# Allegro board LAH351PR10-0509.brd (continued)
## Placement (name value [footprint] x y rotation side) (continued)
CV1068  10U_0603_6.3V6M~D  [C_0603]  130.24 151.22 180 bottom
CV1069  0.1U_0201_6.3V6K  [C_0201]  131.06 151.06 90 bottom
CV1071  10P_0402_50V8J  [C_0402]  40.64 143.3 270 top
CV1074  10P_0402_50V8J  [C_0402]  101.73 138.64 90 bottom
CV1075  10P_0402_50V8J  [C_0402]  30.9 140.97 180 bottom
CV1076  10U_0603_6.3V6M  [C_0603]  31.11 140.01 270 bottom
CV1077  10U_0603_6.3V6M  [C_0603]  32.26 139.35 0 bottom
CV1078  47U_0603_6.3V6M  [C_0603]  28.64 139.91 0 bottom
CV1079  10U_0603_6.3V6M  [C_0603]  28.64 138.7 0 bottom
CV1080  10P_0402_50V8J  [C_0402]  29.12 141 180 bottom
CV1081  2200P_0402_25V7K  [C_0402]  27.22 140.08 270 bottom
CV7160  0.1U_0402_16V4Z  [C_0402]  80.31 14.12 0 bottom
CV7161  4.7U_0402_6.3V6M  [C_0402]  80.31 13.11 0 bottom
CX1  0.1U_0402_16V7K  [C_0402]  121.87 142.78 180 top
CX2  0.1U_0402_16V7K  [C_0402]  129.84 143.22 0 top
CZ120  0.1U_0402_10V7K  [C_0402]  81.32 6.78 270 bottom
CZ121  470P_0402_50V7K  [C_0402]  82.27 9.76 90 bottom
DE1  SDMK0340L-7-F_SOD323-2~D  [SDMK0340L-7-F_SOD323-2]  115.44 20.21 270 bottom
DE2  -  [RB751V-40_SOD323-2]  74.23 7.4 90 top
DE3  -  [RB751V-40_SOD323-2]  72.58 7.4 90 top
DF1  -  [SDMK0340L-7-F_SOD323-2]  85.28 21.68 270 top
DF2  -  [SDMK0340L-7-F_SOD323-2]  87 21.68 270 top
DG2  RB751S40T1G_SOD523-2  [RB520SM-30T2R_EMD2-2]  61.82 76.8 90 top
DG3  RB751S40T1G_SOD523-2  [RB520SM-30T2R_EMD2-2]  77.6 57.27 270 bottom
DG4  RB751S40T1G_SOD523-2  [RB520SM-30T2R_EMD2-2]  77.6 59.25 90 bottom
DG7  RB751S40T1G_SOD523-2  [RB520SM-30T2R_EMD2-2]  76.33 57.27 270 bottom
DG8  RB751S40T1G_SOD523-2  [RB520SM-30T2R_EMD2-2]  98.33 55.11 180 top
DG9  RB751S40T1G_SOD523-2  [RB520SM-30T2R_EMD2-2]  95.53 53.64 90 top
DG10  RB751S40T1G_SOD523-2  [RB520SM-30T2R_EMD2-2]  73.24 56.86 90 bottom
DH1  -  [RB751V-40_SOD323-2]  111.76 17.75 90 top
DK1  -  [TVNST52302AB0_SOT523-3]  89.04 9.5 0 top
DK2  -  [TVNST52302AB0_SOT523-3]  70.1 82.07 0 bottom
DK3  -  [TVNST52302AB0_SOT523-3]  81.85 11.58 90 bottom
DT1  SDM10U45-7_SOD523-2~D  [RB520SM-30T2R_EMD2-2]  100.27 145.74 90 bottom
DT2  -  [PESD5V0H1BSF_SOD962-2-2]  91 148.67 90 bottom
DT3  -  [PESD5V0H1BSF_SOD962-2-2]  91 147.93 270 bottom
DT4  -  [PESD5V0H1BSF_SOD962-2-2]  94.24 147.22 180 top
DT5  -  [PESD5V0H1BSF_SOD962-2-2]  94.99 147.22 0 top
DT6  -  [PESD5V0H1BSF_SOD962-2-2]  99.37 147.22 0 top
DT7  -  [PESD5V0H1BSF_SOD962-2-2]  98.62 147.22 180 top
DT8  -  [PESD5V0H1BSF_SOD962-2-2]  99.18 148.87 0 bottom
DT9  -  [PESD5V0H1BSF_SOD962-2-2]  98.5 148.87 180 bottom
DT10  -  [TVWDF1004AD0_DFN9]  102.88 148.79 270 bottom
DT11  -  [PESD5V0H1BSF_SOD962-2-2]  95.96 151.92 180 bottom
DT12  -  [PESD5V0H1BSF_SOD962-2-2]  97.15 147.22 0 top
DT13  -  [PESD5V0H1BSF_SOD962-2-2]  97.65 151.92 0 bottom
DT14  -  [PESD5V0H1BSF_SOD962-2-2]  96.07 147.22 0 top
DT15  -  [PESD24VS2UT_SOT23-3]  105.22 145.39 0 bottom
DT16  -  [PESD5V0H1BSF_SOD962-2-2]  138.88 55.93 180 bottom
DU6  -  [SDMK0340L-7-F_SOD323-2]  82.87 6.44 0 bottom
DU8  -  [SDMK0340L-7-F_SOD323-2]  87.63 10.5 270 bottom
DV1  -  [RB751V-40_SOD323-2]  24.93 133.96 90 top
DV4  -  [AZC199-02SPR7G_SOT23-3]  66.97 138.85 270 bottom
DV12  SDM10U45-7_SOD523-2  [RB520SM-30T2R_EMD2-2]  136.68 151.28 180 bottom
DV13  SDM10U45-7_SOD523-2  [RB520SM-30T2R_EMD2-2]  136.68 150.01 180 bottom
FD1  FIDUCIAL  [FIDUCIAL_C40M80]  11.49 138.46 0 top
FD2  FIDUCIAL  [FIDUCIAL_C40M80]  146.56 35.02 0 top
FD3  FIDUCIAL  [FIDUCIAL_C40M80]  12.51 138.46 180 bottom
FD4  FIDUCIAL  [FIDUCIAL_C40M80]  125.22 11.08 180 bottom
FV2  1.1A_6V_SPR-P110  [F_SPR-P110]  103.93 143.54 0 top
FV3  1.1A_6V_SPR-P110  [F_SPR-P110]  128.25 149.63 0 bottom
FV4  1.5A_24V_SMD1812P150TF-24  [F_SMD1812P150TF-24]  34.49 142.78 180 top
H1  -  [H_4P0]  149.5 114.4 0 top
H2  -  [H_3P7-G]  144.9 80.1 0 top
H3  -  [H_2P6-G]  140 44.5 0 top
H4  -  [H_2P6-G]  42.4 2.5 0 top
H5  -  [H_2P6-G]  7 44.5 0 top
H6  -  [H_4P3X3P7-G]  7.6 66.7 0 top
H7  -  [H_4P0-G]  6.5 140 0 top
H10  -  [H_2P6-G]  87.67 152.7 0 top
H11  -  [H_2P6-G]  106 152.7 0 top
H12  -  [H_1P8]  122.3 149.75 90 top
H13  -  [H_2P6-G]  142.89 149.6 0 top
H14  -  [H_4P0-G]  70.5 128.95 0 top
H15  -  [H_4P0-G]  66.1 68.3 0 top
J4  -  [JUMP_43X79]  63.08 11.27 0 bottom
J5  -  [JUMP_43X79]  72.88 11.78 180 bottom
J6  -  [JUMP_43X79]  103.1 17.43 180 top
JCDRA  TE_2260531-1  [TE_2260531-1_46P]  54.6 149.25 180 top
JDP  ACON_MAR2A-2061801  [ACON_MAR2A-2061801_20P]  112.2 145.82 180 top
JEDP  ACES_50473-0400M-P01  [ACES_50473-0400M-P01_40P]  55.75 151.32 180 bottom
JELC2  CVILU_CH51102M100-0P  [CVILU_CH51102M100-0P_10P-T]  132.95 15.52 90 top
JFAN1  CVILU_CI4204M2HR0-NH  [CVILU_CI4204M2HR0-NH_4P]  14.86 50.89 90 bottom
JFAN2  CVILU_CI4204M2HR0-NH  [CVILU_CI4204M2HR0-NH_4P]  145.05 46.43 270 bottom
JGYRO  ACES_50208-00601-P01  [ACES_50208-00601-P01_6P]  25.12 132.61 270 bottom
JHDMI  ACON_HMRF5-AK1L0C  [ACON_HMRF5-AK1L0C_19P]  127.8 145.68 180 top
JIO1  UNIMI_FBGCAX011  [UNIMI_FBGCAX011_68P-T]  10.66 5.44 90 bottom
JIO2  UNIMI_FBGCAX011  [UNIMI_FBGCAX011_68P-T]  142.34 35.96 270 bottom
JP1  PAD-OPEN 43X39  [JUMP_43X39]  93.61 39.78 180 bottom
JPCMC  INTEL_CMC_PRIMARY  [INTEL_CMC_PRIMARY_36P-T]  147.44 144.74 0 top
JPK  CVILU_CF5020FD0RK-05-NH  [CVILU_CF5020FD0RK-05-NH_20P]  76.45 7.42 180 bottom
JPTRON  ACES_50208-01201-P01  [ACES_50208-01201-P01_12P-T]  51.71 1.5 0 bottom
JRTC1  TWVM_WTB1220-02RD-MAGHB  [TWVM_WTB1220-02RD-MAGHB_2P]  17.73 13.07 180 bottom
JSSD1  LOTES_YPCI0020-P001A  [LOTES_YPCI0020-P001A_75P-T]  111.85 8.87 0 top
JSSD3  LOTES_YPCI0020-P001A  [LOTES_YPCI0020-P001A_75P-T]  136.65 8.87 0 top
JTOBII  HRS_DF52-6S-0P8H(21)  [HRS_DF52-6S-0P8H-21_6P-T]  142.92 142.31 270 bottom
JTP15  STARC_106A08-001020-A2-R  [STARC_106A08-001020-A2-R_8P]  76.16 4.73 0 top
JTP17  ACES_51678-0080N-001  [ACES_51678-0080N-001_8P-T]  60.31 5.93 0 top
JUSBC  JAE_DX07SA24XJ2R1000~D  [JAE_DX07SA24XJ2R1000_24P]  99.58 148.79 180 top
JWDB  ACES_88266-04001  [ACES_50207-00471-P01_4P-T]  123.35 43.61 270 top
JWDB1  ACES_88266-04001  [ACES_50207-00471-P01_4P-T]  135.87 15.86 270 top
LE1  FBMA-L11-160808-800LMT_0603  [KC_FBMA-L11-160808-800LMT_2P]  76.89 20.54 180 top
LE3  DLM0NSN900HY2D_4P  [MURAT_DLM0NSN900HY2D_4P]  140.16 140.24 0 bottom
LE4  BLM15AG121SN1D_L0402_2P  [MURAT_BLM15AG121SN1D_L0402_2P]  128.52 26.04 270 bottom
LE5  FBMA-L11-160808-800LMT_0603  [KC_FBMA-L11-160808-800LMT_2P]  73.35 19.01 0 top
LE7  DLM0NSN900HY2D_4P  [MURAT_DLM0NSN900HY2D_4P]  89.94 11.19 270 top
LG1  PBY160808T-301Y-N  [CHILI_PBY160808T-300Y-N_2P]  51.65 104.58 0 bottom
LG6  PBY160808T-300Y-N_2P  [CHILI_PBY160808T-300Y-N_2P]  50.53 111.28 0 bottom
LG8  PBY160808T-300Y-N_2P  [CHILI_PBY160808T-300Y-N_2P]  50.25 87.9 0 bottom
LG9  PBY160808T-300Y-N_2P  [CHILI_PBY160808T-300Y-N_2P]  59.83 94.26 180 bottom
LG10  PBY160808T-300Y-N_2P  [CHILI_PBY160808T-300Y-N_2P]  59.77 97.06 180 bottom
LM1  DLM0NSN900HY2D_4P  [MURAT_DLM0NSN900HY2D_4P]  38.1 145.58 90 top
LT1  0.6UH_MND-04ABIR60M-XGL_20%  [MAG_MND-04ABIR60M-XGL_2P]  71.35 148.49 0 top
LT2  DLM0NSN900HY2D_4P  [MURAT_DLM0NSN900HY2D_4P]  95.81 143.17 90 top
LT3  DLM0NSN900HY2D_4P  [MURAT_DLM0NSN900HY2D_4P]  97.41 143.17 90 top
LT4  1UH_LQM18PN1R0MFHD_20%  [MURAT_LQM18PN1R0MFHD_2P]  84.71 145.75 90 top
LV2  DLM0NSN900HY2D_4P  [MURAT_DLM0NSN900HY2D_4P]  66 134.8 90 bottom
LV3  HCM1012GH900BP_4P  [INPAQ_HCM1012GH900BP_4P-NPM]  138.36 139.99 90 bottom
LV4  HCM1012GH900BP_4P  [INPAQ_HCM1012GH900BP_4P-NPM]  134.11 140.06 90 bottom
LV5  HCM1012GH900BP_4P  [INPAQ_HCM1012GH900BP_4P-NPM]  124.58 139.93 90 bottom
LV6  HCM1012GH900BP_4P  [INPAQ_HCM1012GH900BP_4P-NPM]  129.35 139.99 90 bottom
LX1  PBY100505T-601Y-N_2P  [CHILI_PBY100505T-300Y-N_2P]  135.64 138.21 90 bottom
LX2  PBY100505T-601Y-N_2P  [CHILI_PBY100505T-300Y-N_2P]  132.14 138.21 90 bottom
LX3  PBY100505T-601Y-N_2P  [CHILI_PBY100505T-300Y-N_2P]  140.4 138.21 90 bottom
LX4  PBY100505T-601Y-N_2P  [CHILI_PBY100505T-300Y-N_2P]  136.84 138.21 90 bottom
LX5  PBY100505T-601Y-N_2P  [CHILI_PBY100505T-300Y-N_2P]  126.17 138.21 90 bottom
LX6  PBY100505T-601Y-N_2P  [CHILI_PBY100505T-300Y-N_2P]  122.62 138.21 90 bottom
LX7  PBY100505T-601Y-N_2P  [CHILI_PBY100505T-300Y-N_2P]  130.94 138.21 90 bottom
LX8  PBY100505T-601Y-N_2P  [CHILI_PBY100505T-300Y-N_2P]  127.38 138.21 90 bottom
NOREF  -  []  7.6 66.7 0 top
NOREF#2  -  []  42.4 2.5 0 top
NOREF#3  -  []  140 44.5 0 top
NOREF#4  -  []  142.89 149.6 0 top
NOREF#5  -  []  6.5 140 0 top
NOREF#6  -  []  21.34 199.93 0 top
NOREF#7  -  []  87.67 152.7 0 top
NOREF#8  -  []  70.5 128.95 0 top
NOREF#9  -  []  7 44.5 0 top
NOREF#10  -  []  82.79 82.54 270 top
NOREF#11  -  []  55.19 -33.83 0 top
NOREF#12  -  []  162.94 52.22 0 top
NOREF#13  -  []  65.28 -31.95 0 top
NOREF#14  -  []  106 152.7 0 top
NOREF#15  -  []  66.1 68.3 0 top
NOREF#16  -  []  149.5 114.4 0 top
NOREF#17  -  []  0 157 0 top
NOREF#18  -  []  0 157 0 top
NOREF#19  -  []  104.33 81.05 0 top
NOREF#20  -  []  0 157 0 top
NOREF#21  -  []  144.9 80.1 0 top
NOREF#22  -  []  122.75 77.5 0 top
NOREF#23  -  []  132.03 47.75 180 bottom
NOREF#24  -  []  42.08 17.24 90 bottom
NOREF#25  -  []  132.94 79.68 270 bottom
PBATT1  OCTEK_WTB-10FPBLAB-U  [OCTEK_WTB-10FPBLAB-U_10P]  24.58 9.95 180 bottom
PC1  100P_0402_50V8J  [C_0402]  10.54 37.1 90 bottom
PC2  1000P_0402_50V7K  [C_0402]  9.59 37.1 90 bottom
PC3  100P_0402_50V8J  [C_0402]  11.37 26.84 270 bottom
PC4  1000P_0402_50V7K  [C_0402]  12.32 26.84 270 bottom
PC6  1000P_0402_50V7K  [C_0402]  32.7 4.83 270 top
PC7  100P_0402_50V8J  [C_0402]  36.07 4.77 270 top
PC8  1000P_0402_50V7K  [C_0402]  37.5 9.68 0 top
PC9  100P_0402_50V8J  [C_0402]  37.5 10.76 0 top
PC13  .1U_0402_16V7K  [C_0402]  50.1 12.27 90 top
PC14  1U_0603_25V6K  [C_0603]  25.87 4.9 180 top
PC15  0.1U_0402_25V6  [C_0402]  17.54 1.93 180 top
PC301  1U_0402_25V6K  [C_0402]  67.28 34.58 0 top
PC302  22U_0603_6.3V6M  [C_0603]  60.77 18.76 90 bottom
PC303  22U_0603_6.3V6M  [C_0603]  63.18 18.76 90 bottom
PC304  22U_0603_6.3V6M  [C_0603]  61.98 18.76 90 bottom
PC305  22U_0603_6.3V6M  [C_0603]  64.39 18.76 90 bottom
PC306  22U_0603_6.3V6M  [C_0603]  65.6 18.76 90 bottom
PC307  10U_0603_25V6M  [C_0603]  65.34 28.54 180 top
PC308  10U_0603_25V6M  [C_0603]  65.34 28.54 180 bottom
PC309  4.7U_0402_6.3V6M  [C_0402]  60.34 21.92 0 top
PC310  680P_0402_50V7K  [C_0402]  65.21 26.72 0 bottom
PC311  1000P_0402_25V8J  [C_0402]  64.14 34.14 270 bottom
PC312  0.1U_0402_25V6  [C_0402]  65.42 29.68 180 bottom
PC313  1000P_0402_25V8J  [C_0402]  59.94 24.42 270 bottom
PC314  2200P_0402_50V7K  [C_0402]  65.41 29.68 180 top
PC315  .1U_0402_16V7K  [C_0402]  68.16 23.05 270 top
PC501  1U_0402_25V6K  [C_0402]  59.66 35.89 180 top
PC502  22U_0603_6.3V6M  [C_0603]  56.07 14.82 90 bottom
PC503  22U_0603_6.3V6M  [C_0603]  56.07 13.17 270 bottom
PC504  22U_0603_6.3V6M  [C_0603]  53.53 14.82 90 bottom
PC505  22U_0603_6.3V6M  [C_0603]  54.8 14.82 90 bottom
PC506  22U_0603_6.3V6M  [C_0603]  54.8 13.17 270 bottom
PC507  22U_0603_6.3V6M  [C_0603]  53.53 13.17 270 bottom
PC508  10U_0603_25V6M  [C_0603]  57.02 27.59 180 top
PC509  10U_0603_25V6M  [C_0603]  59.44 26.82 0 top
PC510  4.7U_0402_6.3V6M  [C_0402]  54.37 21.87 180 bottom
PC511  4.7U_0402_6.3V6M  [C_0402]  41.85 9.69 270 bottom
PC512  4.7U_0402_6.3V6M  [C_0402]  54.39 22.81 180 bottom
PC513  680P_0402_50V7K  [C_0402]  52.83 19.71 0 bottom
PC514  1000P_0402_25V8J  [C_0402]  59.96 34.98 180 top
PC515  0.1U_0402_25V6  [C_0402]  56.72 26.49 180 top
PC516  1000P_0402_25V8J  [C_0402]  50.86 24.04 270 top
PC517  2200P_0402_50V7K  [C_0402]  59.63 25.75 0 top
PC518  .1U_0402_16V7K  [C_0402]  58.11 18.51 270 bottom
PC1101  22U_0603_6.3V6M  [C_0603]  67.43 114.35 90 bottom
PC1102  22U_0603_6.3V6M  [C_0603]  66.17 114.39 90 bottom
PC1103  22U_0603_6.3V6M  [C_0603]  68.75 114.35 90 bottom
PC1104  22U_0603_6.3V6M  [C_0603]  64.9 114.39 90 bottom
PC1105  4.7U_0402_6.3V6M  [C_0402]  68.34 107.53 180 bottom
PC1106  10U_0603_25V6M  [C_0603]  74.17 103.28 270 bottom
PC1107  1U_0402_25V6K  [C_0402]  80.45 98.12 90 bottom
PC1108  2.2U_0402_6.3V6M  [C_0402]  68.34 106.58 180 bottom
PC1109  0.1U_0402_50V7K  [C_0402]  71.95 109.77 180 top
PC1110  1000P_0402_50V7K  [C_0402]  79.5 98.12 90 bottom
PC1111  330P_0402_50V7K  [C_0402]  66.6 103.98 0 bottom
PC1112  680P_0402_50V7K  [C_0402]  68.97 108.21 0 top
PC1113  0.1U_0402_16V7K  [C_0402]  69.98 101.84 270 bottom
PC1114  0.1U_0402_25V6  [C_0402]  76.16 101.54 180 bottom
PC1115  2200P_0402_50V7K  [C_0402]  76.19 102.47 180 bottom
PC1808  22U_0603_6.3V6M  [C_0603]  57.66 7.27 0 top
PC1809  22U_0603_6.3V6M  [C_0603]  58.93 9.17 90 top
PC1810  22U_0603_6.3V6M  [C_0603]  57.59 9.17 90 top
PC1811  22U_0603_6.3V6M  [C_0603]  56.26 9.17 90 top
PC1812  4.7U_0402_6.3V6M  [C_0402]  50.63 4.75 90 top
PC1813  10U_0603_25V6M  [C_0603]  48.32 9.55 90 top
PC1814  10U_0603_25V6M  [C_0603]  47.12 9.55 90 top
PC1815  1U_0402_25V6K  [C_0402]  40.72 6.89 180 top
PC1816  2.2U_0402_6.3V6M  [C_0402]  52.06 2.38 0 top
PC1817  0.1U_0603_25V7K  [C_0603]  50.85 11.25 270 top
PC1818  1000P_0402_50V7K  [C_0402]  41.63 7.14 90 top
PC1819  330P_0402_50V7K  [C_0402]  51.12 1.98 90 top
PC1820  680P_0402_50V7K  [C_0402]  53.66 10.44 270 top
PC1821  0.1U_0402_16V7K  [C_0402]  47.57 3.46 180 top
PC2501  0.1U_0402_16V7K  [C_0402]  85.02 59.27 270 top
PC2502  22U_0603_6.3V6M  [C_0603]  87.44 58.01 0 top
PC2503  22U_0603_6.3V6M  [C_0603]  87.39 59.4 0 top
PC2504  22P_0603_50V8  [C_0603]  86.16 70.21 270 top
PC2505  22U_0603_6.3V6M  [C_0603]  87.65 70.21 90 top
PC2506  22U_0603_6.3V6M  [C_0603]  89.05 70.15 90 top
PC2507  2.2U_0402_6.3V6K  [C_0402]  89.91 60.62 0 top
PC2508  0.1U_0402_25V6  [C_0402]  45.02 9.79 90 top
PC2509  2200P_0402_50V7K  [C_0402]  45.97 9.79 90 top
PC2510  0.1U_0402_25V6  [C_0402]  50.06 25.16 270 bottom
PC2511  2200P_0402_50V7K  [C_0402]  49.17 25.12 180 bottom
PC2512  22U_0805_25V6M  [C_0805]  131.48 43.28 0 bottom
PC2513  0.01U_0402_50V7K  [C_0402]  139.13 38.14 270 bottom
PC2514  100P_0402_50V8J  [C_0402]  134.29 34.44 0 bottom
PC2515  330P_0402_50V8J  [C_0402]  139.88 33.76 90 bottom
PC2516  1U_0402_6.3V6K  [C_0402]  136.19 40.29 0 bottom
PC2517  680P_0402_50V7K  [C_0402]  134.66 36.22 270 bottom
PC2518  22U_0603_6.3V6M  [C_0603]  140.18 39.59 270 bottom
PC2519  22U_0805_25V6M  [C_0805]  131.48 41.56 0 bottom
PC2520  0.1U_0402_25V6  [C_0402]  47.99 36.76 180 top
PC2521  2200P_0402_50V7K  [C_0402]  47.98 37.71 180 top
PCA1  2.2U_0402_25V6M  [C_0402]  141.38 98.75 180 bottom
PCA2  2.2U_0402_25V6M  [C_0402]  140.9 102.32 90 bottom
PCA3  0.1U_0402_25V6  [C_0402]  148.1 98.17 180 top
PCA4  0.22U_0603_25V7K  [C_0603]  144.89 98.14 0 top
PCA6  10U_0603_25V6M  [C_0603]  149.08 98.78 0 top
PCA7  10U_0603_25V6M  [C_0603]  149.06 100.56 0 top
PCA9  390P_0402_50V7K  [C_0402]  143.62 104.45 0 bottom
PCA10  1U_0402_25V6K  [C_0402]  150.9 104.9 90 top
PCA11  1000P_0402_50V7K  [C_0402]  150.9 103.91 270 top
PCA12  2200P_0402_50V7K  [C_0402]  149.94 101.91 0 top
PCB1  0.1U_0402_25V6  [C_0402]  25.02 14.75 90 bottom
PCB2  0.1U_0402_25V6  [C_0402]  47.61 22.16 180 bottom
PCB3  0.1U_0402_25V6  [C_0402]  22.52 24.98 180 top
PCB4  0.1U_0402_25V6  [C_0402]  42.04 12.17 270 bottom
PCB5  0.1U_0402_25V6  [C_0402]  29.1 5.36 270 top
PCB6  0.1U_0402_25V6  [C_0402]  51.05 16.65 90 bottom
PCB7  0.1U_0402_25V6  [C_0402]  27.05 18.58 270 top
PCB8  0.47U_0402_25V6K  [C_0402]  39.31 22.01 270 bottom
PCB9  10U_0603_25V6M  [C_0603]  24.98 11.8 90 top
PCB10  10U_0603_25V6M  [C_0603]  26.1 14.51 90 bottom
PCB11  10U_0603_25V6M  [C_0603]  34.99 4.82 270 top
PCB12  10U_0603_25V6M  [C_0603]  28.03 5.32 270 top
PCB13  10U_0603_25V6M  [C_0603]  27.37 14.51 90 bottom
PCB14  10U_0603_25V6M  [C_0603]  24.97 10.18 270 top
PCB15  10U_0603_25V6M  [C_0603]  29.91 14.51 90 bottom
PCB16  10U_0603_25V6M  [C_0603]  28.65 14.49 90 bottom
PCB17  10U_0603_25V6M  [C_0603]  33.78 4.82 270 top
PCB18  0.22U_0603_25V7K  [C_0603]  43.97 19.71 0 top
PCB19  0.033U_0402_25V7K  [C_0402]  47.94 12.72 90 top
PCB20  0.033U_0402_25V7K  [C_0402]  48.55 21.77 0 bottom
PCB21  2.2U_0603_25V6K  [C_0603]  41.15 16.09 180 bottom
PCB22  2.2U_0402_16V6K  [C_0402]  40.06 17.17 0 bottom
PCB23  2.2U_0402_16V6K  [C_0402]  40.97 18.13 180 bottom
PCB24  680P_0402_50V7K  [C_0402]  36.39 25.22 90 bottom
PCB25  1000P_0402_25V8J  [C_0402]  22.19 14.76 90 bottom
PCB26  0.022U_0402_25V7K  [C_0402]  23.11 14.75 90 bottom
PCB27  10P_0402_50V8J  [C_0402]  44.5 11.84 0 bottom
PCB28  2200P_0402_50V7K  [C_0402]  21.27 14.76 90 bottom
PCB29  2200P_0402_50V7K  [C_0402]  24.07 14.75 90 bottom
PCB30  560P_0402_50V7K  [C_0402]  47.05 13.63 270 bottom
PCB31  0.01UF_0402_25V7K  [C_0402]  50.18 19.9 180 bottom
PCB32  0.01U_0402_25V7K  [C_0402]  45.69 22.16 90 bottom
PCB33  2200P_0402_25V7K  [C_0402]  51.06 15.74 270 bottom
PCB34  1200P_0402_50V7K  [C_0402]  19.51 26 0 top
PCB35  0.1U_0402_25V6  [C_0402]  141.1 107.1 0 top
PCG01  2200P_0402_50V7K  [C_0402]  150.42 85.71 270 top
PCG02  0.1U_0402_25V6  [C_0402]  150.39 86.9 90 top
PCG03  10U_0603_25V6M  [C_0603]  149.05 85.61 270 top
PCG04  10U_0603_25V6M  [C_0603]  149.09 86.88 90 top
PCG07  2.2U_0402_25V6M  [C_0402]  141.03 83.67 270 top
PCG8  2.2U_0402_25V6M  [C_0402]  141.03 86.18 90 top
PCG09  0.22U_0603_25V7K  [C_0603]  140.3 86.82 270 bottom
PCG10  390P_0402_50V7K  [C_0402]  144.34 93.03 0 bottom
PCG11  1000P_0402_50V7K  [C_0402]  149.82 79.05 180 top
PCG12  1U_0402_25V6K  [C_0402]  149.81 77.12 180 top
PCH1  0.1U_0402_25V6  [C_0402]  134.05 24.91 90 top
PCH2  10U_0603_25V6M  [C_0603]  135.13 24.73 90 top
PCH3  10U_0603_25V6M  [C_0603]  132.91 27.33 0 bottom
PCH4  1U_0402_25V6K  [C_0402]  139.76 22.49 90 top
PCH5  0.1U_0603_25V7K  [C_0603]  134.34 31.3 90 top
PCH6  1000P_0402_50V7K  [C_0402]  143.38 22.49 90 top
PCH7  2200P_0402_50V7K  [C_0402]  133.15 28.48 0 bottom
PCH8  680P_0402_50V7K  [C_0402]  131.01 25.49 180 bottom
PCH9  0.1U_0402_16V7K  [C_0402]  140.91 29.9 270 top
PCH10  1U_0603_6.3V6M  [C_0603]  135.52 33.32 0 top
PCH11  330U_D2_2VM_R9M  [C_D2]  125.16 30.42 90 bottom
PCH12  330U_D2_2VM_R9M  [C_D2]  125.22 36.26 0 top
PCH13  0.1U_0402_25V6  [C_0402]  132.82 48.71 90 top
PCH14  22U_0603_6.3V6M  [C_0603]  122.07 53.72 90 top
PCH15  22U_0603_6.3V6M  [C_0603]  122.04 50.88 270 bottom
PCH16  22U_0603_6.3V6M  [C_0603]  122.05 53.74 90 bottom
PCH17  22U_0603_6.3V6M  [C_0603]  122.06 50.89 270 top
PCH18  4.7U_0402_6.3V6M  [C_0402]  133.22 53.57 270 bottom
PCH19  10U_0603_25V6M  [C_0603]  135.01 49.42 0 top
PCH20  1U_0402_25V6K  [C_0402]  136.35 48.86 180 bottom
PCH21  2.2U_0402_6.3V6M  [C_0402]  134.18 53.57 270 bottom
PCH22  680P_0402_50V7K  [C_0402]  131.83 51.46 0 bottom
PCH23  0.1U_0402_50V7K  [C_0402]  130.63 50.07 180 bottom
PCH24  1000P_0402_50V7K  [C_0402]  135.69 45.52 270 top
PCH25  2200P_0402_50V7K  [C_0402]  134.77 48.36 0 top
PCH26  330P_0402_50V7K  [C_0402]  133.5 56.58 270 top
PCH27  0.22U_0402_10V6K  [C_0402]  138.23 53.49 0 top
PCH28  0.1U_0402_25V6  [C_0402]  134.18 47.45 0 top
PCM1  0.1U_0402_25V6  [C_0402]  146.04 38.47 0 top
PCM2  0.1U_0402_25V6  [C_0402]  145.35 52.87 270 bottom
PCM3  0.1U_0402_25V6  [C_0402]  142.4 40.36 180 top
PCM4  10U_0603_25V6M  [C_0603]  141.81 52.67 270 bottom
PCM5  10U_0603_25V6M  [C_0603]  141.8 54.26 90 bottom
PCM6  10U_0603_25V6M  [C_0603]  143.12 52.66 270 bottom
PCM7  10U_0603_25V6M  [C_0603]  143.13 54.26 90 bottom
PCM8  10U_0603_6.3V6M  [C_0603]  143.89 50 270 top
PCM9  10U_0603_6.3V6M  [C_0603]  143.89 50 270 bottom
PCM10  1U_0402_25V6K  [C_0402]  134.8 45.52 270 top
PCM11  2.2U_0402_6.3V6M  [C_0402]  150.72 45.79 90 top
PCM12  0.1U_0603_25V7K  [C_0603]  150.75 54.74 90 top
PCM13  1000P_0402_50V7K  [C_0402]  136.35 49.75 180 bottom
PCM14  2200P_0402_50V7K  [C_0402]  145.22 57.17 90 bottom
PCM15  680P_0402_50V7K  [C_0402]  151.07 60.28 90 bottom
PCM16  0.033U_0402_16V7K  [C_0402]  143.77 47.65 180 top
PCM17  1U_0603_10V6K  [C_0603]  150.6 49.1 270 top
PCM18  0.1U_0402_10V7K  [C_0402]  146.67 43.88 270 top
PCM19  0.1U_0402_10V7K  [C_0402]  146.73 41.99 0 top
PCM20  470U_D2E_2.5VM_R6M  [C_D2E]  149.35 66.95 90 bottom
PCV1  0.1U_0402_25V6  [C_0402]  77.79 24.49 270 top
PCV3  0.1U_0402_25V6  [C_0402]  74.74 24.49 270 top
PCV4  0.1U_0402_25V6  [C_0402]  81.22 28.84 90 bottom
PCV5  0.1U_0402_25V6  [C_0402]  80.11 32.66 180 top
PCV6  0.1U_0402_25V6  [C_0402]  76.77 33.91 90 top
PCV7  0.1U_0402_25V6  [C_0402]  75.76 24.49 270 top
PCV8  0.1U_0402_25V6  [C_0402]  77.29 28.54 180 bottom
PCV9  0.1U_0402_25V6  [C_0402]  70.68 24.49 270 top
PCV10  0.1U_0402_25V6  [C_0402]  79.17 30.57 0 top
PCV11  0.1U_0402_25V6  [C_0402]  72.71 24.49 270 top
PCV12  0.1U_0402_25V6  [C_0402]  80.07 35.54 270 top
PCV13  0.1U_0402_25V6  [C_0402]  76.92 32.3 270 bottom
PCV14  0.1U_0402_25V6  [C_0402]  76.77 24.49 270 top
PCV15  0.1U_0402_25V6  [C_0402]  71.69 24.49 270 top
PCV16  0.1U_0402_25V6  [C_0402]  73.72 24.49 270 top
PCV18  1U_0402_16V6K  [C_0402]  72.48 29.73 180 bottom
PCV19  4.7U_0402_6.3V6M  [C_0402]  73.28 26.24 90 bottom
PCV20  4700P_0402_50V7K  [C_0402]  68.19 32.78 0 bottom
PCV21  0.015U_0402_16V7K  [C_0402]  81.28 33.63 270 bottom
PCV22  0.022U_0603_50V7K  [C_0603]  59.12 26.38 0 bottom
PCV23  2.2U_0402_6.3V6M  [C_0402]  52.65 32.6 180 bottom
PCV24  2.2U_0402_6.3V6M  [C_0402]  57.66 30.75 0 top
PCV26  2.2U_0603_25VX7SK  [C_0603]  49.4 26.27 180 bottom
PCV27  2.2U_0603_25VX7SK  [C_0603]  18.05 33.26 90 top
PCV28  2.2U_0603_25VX7SK  [C_0603]  19.27 33.49 90 top
PCV29  2.2U_0603_25VX7SK  [C_0603]  21.67 33.52 90 top
PCV30  2.2U_0603_25VX7SK  [C_0603]  49.39 29.9 180 bottom
PCV31  2.2U_0603_25VX7SK  [C_0603]  49.39 28.68 180 bottom
PCV32  2.2U_0603_25VX7SK  [C_0603]  20.46 33.52 90 top
PCV33  2.2U_0603_25VX7SK  [C_0603]  49.4 27.47 180 bottom
PCV34  1U_0402_25V6K  [C_0402]  51.59 29.09 0 bottom
PCV35  1U_0402_25V6K  [C_0402]  51.59 30.04 0 bottom
PCV36  1U_0402_25V6K  [C_0402]  57.49 37.33 0 top
PCV37  1U_0402_25V6K  [C_0402]  59.39 34.67 180 bottom
PCV38  0.47U_0402_25V6K  [C_0402]  54.48 34.18 90 top
PCV39  0.47U_0402_25V6K  [C_0402]  53.68 29.99 0 top
PCV40  680P_0402_50V7K  [C_0402]  51.1 23.31 180 bottom
PCV41  1000P_0402_50V7K  [C_0402]  56.32 27.35 270 bottom
PCV42  560P_0402_50V7K  [C_0402]  57.28 27.35 270 bottom
PCV43  22U_B2_25VM_R100M  [C_B2]  46.91 36.9 0 bottom
PCV44  22U_B2_25VM_R90M  [C_B2]  20.59 31.61 90 top
PCV48  0.1U_0402_25V6  [C_0402]  38.02 40.4 270 bottom
PCV49  0.1U_0402_25V6  [C_0402]  27.04 40.06 180 top
PCV50  1U_0402_25V6K  [C_0402]  27.04 40.96 180 top
PCV51  1U_0402_25V6K  [C_0402]  38.99 40.43 270 bottom
PCV52  2.2U_0603_25VX7SK  [C_0603]  35.74 40.43 0 top
PCV53  2.2U_0603_25VX7SK  [C_0603]  26.54 43.58 90 bottom
PCV54  2.2U_0603_25VX7SK  [C_0603]  34.71 39.07 180 top
PCV55  2.2U_0603_25VX7SK  [C_0603]  29.59 43.09 90 top
PCV56  2.2U_0603_25VX7SK  [C_0603]  35.61 40.44 270 bottom
PCV57  2.2U_0603_25VX7SK  [C_0603]  27.79 43.55 90 bottom
PCV58  2.2U_0603_25VX7SK  [C_0603]  35.7 39.07 0 top
PCV59  2.2U_0603_25VX7SK  [C_0603]  29.04 43.58 90 bottom
PCV60  0.22U_0603_25V7K  [C_0603]  24.23 40.41 270 top
PCV61  0.22U_0603_25V7K  [C_0603]  32.17 40.35 270 top
PCV62  680P_0402_50V7K  [C_0402]  36.77 48.1 270 bottom
PCV63  680P_0402_50V7K  [C_0402]  29.21 48.1 270 bottom
PCV64  2.2U_0402_6.3V6M  [C_0402]  31.2 44.07 90 bottom
PCV65  2.2U_0402_6.3V6M  [C_0402]  32.88 44.96 270 bottom
PCV66  2.2U_0402_6.3V6M  [C_0402]  25.43 44.07 90 bottom
PCV67  2.2U_0402_6.3V6M  [C_0402]  23.62 44.27 90 bottom
PCV68  2200P_0402_50V7K  [C_0402]  34.33 43.97 90 bottom
PCV69  2200P_0402_50V7K  [C_0402]  34.82 41.02 180 top
PCV70  1000P_0402_25V8J  [C_0402]  34.82 40.13 180 top
PCV71  1000P_0402_25V8J  [C_0402]  35.23 43.97 90 bottom
PCV74  100U_D3L_25VM_R60M  [C_T521D107M025ATE060]  78.36 40.79 90 top
PCV75  100U_D3L_25VM_R60M  [C_T521D107M025ATE060]  63.12 37.47 0 top
PCV76  33U_D2_25VM_R40M  [C_EEFCX1E330R]  78.55 39.5 270 bottom
PCV77  33U_D2_25VM_R40M  [C_EEFCX1E330R]  29.79 40.1 0 bottom
PCV78  470U_D2_2VM_R4.5M  [C_D2]  26.76 55.91 180 bottom
PCV79  470U_D2_2VM_R4.5M  [C_D2]  62.56 60.98 0 top
PCV82  1U_0402_25V6K  [C_0402]  50.18 40.17 180 top
PCV83  1U_0402_25V6K  [C_0402]  45.3 40.45 270 bottom
PCV84  0.1U_0402_25V6  [C_0402]  53.19 40.66 270 bottom
PCV85  0.1U_0402_25V6  [C_0402]  42.35 40.97 180 top
PCV86  2.2U_0603_25VX7SK  [C_0603]  43.33 38.97 0 top
PCV87  2.2U_0603_25VX7SK  [C_0603]  43.35 40.22 0 top
PCV88  2.2U_0603_25VX7SK  [C_0603]  51.3 39.02 0 top
PCV89  2.2U_0603_25VX7SK  [C_0603]  50.11 39.06 180 top
PCV90  2.2U_0603_25VX7SK  [C_0603]  48.77 40.69 270 bottom
PCV91  2.2U_0603_25VX7SK  [C_0603]  42.29 38.97 180 top
PCV92  2.2U_0603_25VX7SK  [C_0603]  47.54 40.69 270 bottom
PCV93  2.2U_0603_25VX7SK  [C_0603]  40.32 40.36 270 bottom
PCV94  0.22U_0603_25V7K  [C_0603]  47.32 38.86 90 top
PCV95  0.22U_0603_25V7K  [C_0603]  39.75 38.85 90 top
PCV96  680P_0402_50V7K  [C_0402]  44.39 48.1 270 bottom
PCV97  680P_0402_50V7K  [C_0402]  52.07 48.1 270 bottom
PCV98  2.2U_0402_6.3V6M  [C_0402]  46.2 44.39 90 bottom
PCV99  2.2U_0402_6.3V6M  [C_0402]  38.62 44.41 90 bottom
PCV100  2.2U_0402_6.3V6M  [C_0402]  40.3 45.05 270 bottom
PCV101  2.2U_0402_6.3V6M  [C_0402]  47.96 45.21 270 bottom
PCV102  1000P_0402_25V8J  [C_0402]  52.27 40.66 270 bottom
PCV103  1000P_0402_25V8J  [C_0402]  42.35 40.05 180 top
PCV104  2200P_0402_50V7K  [C_0402]  46.23 40.46 270 bottom
PCV105  2200P_0402_50V7K  [C_0402]  50.19 41.09 180 top
PCV108  470U_D2_2VM_R4.5M  [C_D2]  61.44 54.45 0 bottom
PCV109  470U_D2_2VM_R4.5M  [C_D2]  61.44 59.27 0 bottom
PCV112  1U_0402_25V6K  [C_0402]  66.79 43.93 90 bottom
PCV113  1U_0402_25V6K  [C_0402]  61.18 40.63 270 bottom
PCV114  1U_0402_25V6K  [C_0402]  67.75 43.89 90 top
PCV115  0.1U_0402_25V6  [C_0402]  57.89 40.19 180 top
PCV116  2.2U_0603_25VX7SK  [C_0603]  59.21 40.58 270 bottom
PCV117  2.2U_0603_25VX7SK  [C_0603]  62.32 40.62 270 bottom
PCV118  2.2U_0603_25VX7SK  [C_0603]  60.17 38.86 270 top
PCV119  2.2U_0603_25VX7SK  [C_0603]  66.03 40.66 270 bottom
PCV120  2.2U_0603_25VX7SK  [C_0603]  57.82 39.12 180 top
PCV121  2.2U_0603_25VX7SK  [C_0603]  57.98 40.58 270 bottom
PCV122  2.2U_0603_25VX7SK  [C_0603]  64.8 40.66 270 bottom
PCV123  2.2U_0603_25VX7SK  [C_0603]  63.56 40.67 270 bottom
PCV124  0.22U_0603_25V7K  [C_0603]  63.87 40.9 0 top
PCV125  0.22U_0603_25V7K  [C_0603]  55.28 39 90 top
PCV126  680P_0402_50V7K  [C_0402]  67.82 48.1 270 bottom
PCV127  680P_0402_50V7K  [C_0402]  59.94 48.22 270 bottom
PCV128  2.2U_0402_6.3V6M  [C_0402]  54.05 44.08 90 bottom
PCV129  2.2U_0402_6.3V6M  [C_0402]  55.73 44.99 270 bottom
PCV130  2.2U_0402_6.3V6M  [C_0402]  63.35 45.13 270 bottom
PCV131  2.2U_0402_6.3V6M  [C_0402]  61.58 44.54 90 bottom
PCV132  1000P_0402_25V8J  [C_0402]  67.7 43.91 90 bottom
PCV133  2200P_0402_50V7K  [C_0402]  65.86 43.97 90 bottom
PCV134  2200P_0402_50V7K  [C_0402]  60.26 40.62 270 bottom
PCV135  1000P_0402_25V8J  [C_0402]  57.87 41.09 180 top
PCV138  470U_D2_2VM_R4.5M  [C_D2]  47.03 55.93 180 bottom
PCV139  470U_D2_2VM_R4.5M  [C_D2]  57.21 55.93 180 bottom
PCV142  1U_0402_25V6K  [C_0402]  71.7 71.97 180 top
PCV143  0.1U_0402_25V6  [C_0402]  70.51 40.2 270 bottom
PCV144  0.1U_0402_25V6  [C_0402]  75.25 43.83 90 top
PCV145  0.1U_0402_25V6  [C_0402]  71.7 73.05 180 top
PCV146  2.2U_0603_25VX7SK  [C_0603]  73.98 71.66 0 top
PCV147  2.2U_0603_25VX7SK  [C_0603]  73.98 72.99 0 top
PCV148  2.2U_0603_25VX7SK  [C_0603]  74.27 40.44 270 bottom
PCV149  2.2U_0603_25VX7SK  [C_0603]  67.94 75.85 90 bottom
PCV150  2.2U_0603_25VX7SK  [C_0603]  74.74 40.22 270 top
PCV151  2.2U_0603_25VX7SK  [C_0603]  66.71 75.9 90 bottom
PCV152  2.2U_0603_25VX7SK  [C_0603]  71.63 40.4 270 bottom
PCV153  2.2U_0603_25VX7SK  [C_0603]  73.47 40.22 270 top
PCV154  0.22U_0603_25V7K  [C_0603]  70.74 41.04 0 top
PCV155  0.22U_0603_25V7K  [C_0603]  70.7 75.77 270 top
PCV156  680P_0402_50V7K  [C_0402]  75.13 48.11 270 bottom
PCV157  680P_0402_50V7K  [C_0402]  75.56 88.55 180 top
PCV158  2.2U_0402_6.3V6M  [C_0402]  71.01 44.97 270 bottom
PCV159  2.2U_0402_6.3V6M  [C_0402]  69.28 44.4 90 bottom
PCV160  2.2U_0402_6.3V6M  [C_0402]  73.37 77.75 180 bottom
PCV161  2.2U_0402_6.3V6M  [C_0402]  76.28 79.36 270 bottom
PCV162  2200P_0402_50V7K  [C_0402]  71.45 76.37 90 bottom
PCV163  1000P_0402_25V8J  [C_0402]  67.88 74.11 180 bottom
PCV164  1000P_0402_25V8J  [C_0402]  69.56 40.2 270 bottom
PCV165  2200P_0402_50V7K  [C_0402]  75.37 43.84 90 bottom
PCV168  470U_D2_2VM_R4.5M  [C_D2]  36.73 55.91 180 bottom
PCV169  470U_D2_2VM_R4.5M  [C_D2]  73.76 83.02 0 bottom
PCV172  47U_0805_4VAM  [C_0805]  35.01 97.18 0 bottom
PCV173  47U_0805_4VAM  [C_0805]  46.49 97.16 0 bottom
PCV174  47U_0805_4VAM  [C_0805]  43.62 97.16 0 bottom
PCV175  10U_0603_6.3V6M  [C_0603]  49.2 101.67 0 bottom
PCV176  22U_0805_6.3VAM  [C_0805]  32.17 97.18 0 bottom
PCV177  22U_0805_6.3VAM  [C_0805]  37.88 97.18 0 bottom
PCV178  22U_0805_6.3VAM  [C_0805]  49.36 97.16 0 bottom
PCV179  22U_0805_6.3VAM  [C_0805]  40.75 97.17 0 bottom
PCV180  10U_0603_6.3VAM  [C_0603]  44.44 98.9 0 bottom
PCV181  10U_0603_6.3VAM  [C_0603]  42.08 98.9 0 bottom
PCV182  10U_0603_6.3VAM  [C_0603]  37.25 98.91 0 bottom
PCV183  10U_0603_6.3VAM  [C_0603]  49.16 100.38 0 bottom
PCV184  10U_0603_6.3VAM  [C_0603]  34.87 100.4 0 bottom
PCV185  10U_0603_6.3VAM  [C_0603]  42.03 100.39 0 bottom
PCV186  10U_0603_6.3VAM  [C_0603]  37.25 100.39 0 bottom
PCV187  10U_0603_6.3VAM  [C_0603]  46.81 101.67 0 bottom
PCV188  10U_0603_6.3VAM  [C_0603]  32.5 101.65 0 bottom
PCV189  10U_0603_6.3VAM  [C_0603]  49.16 98.88 0 bottom
PCV190  10U_0603_6.3VAM  [C_0603]  34.85 98.91 0 bottom
PCV191  10U_0603_6.3VAM  [C_0603]  32.45 98.92 0 bottom
PCV192  10U_0603_6.3VAM  [C_0603]  46.8 98.88 0 bottom
PCV193  10U_0603_6.3VAM  [C_0603]  39.69 98.9 0 bottom
PCV194  10U_0603_6.3VAM  [C_0603]  32.49 100.41 0 bottom
PCV195  10U_0603_6.3VAM  [C_0603]  39.65 100.4 0 bottom
PCV196  10U_0603_6.3VAM  [C_0603]  44.45 100.38 0 bottom
PCV197  10U_0603_6.3VAM  [C_0603]  60.55 64.99 0 bottom
PCV198  10U_0603_6.3VAM  [C_0603]  46.8 100.38 0 bottom
PCV199  10U_0603_6.3VAM  [C_0603]  60.55 62.22 0 bottom
PCV200  10U_0603_6.3VAM  [C_0603]  60.55 63.61 0 bottom
PCV201  10U_0603_6.3VAM  [C_0603]  34.91 101.65 0 bottom
PCV202  470U_D2_2VM_R4.5M  [C_D2]  43.71 93.77 0 bottom
PCV203  470U_D2_2VM_R4.5M  [C_D2]  39.62 93.77 180 bottom
PCV207  1000P_0402_50V7K  [C_0402]  57.61 35.54 270 bottom
PCV208  1U_0402_25V6K  [C_0402]  56.71 35.54 270 bottom
PCV209  0.1U_0402_25V6  [C_0402]  79.17 25.17 0 bottom
PCV210  0.1U_0402_25V6  [C_0402]  79.17 25.3 0 top
PCV211  0.1U_0402_25V6  [C_0402]  79.64 23.59 180 bottom
PCV212  680P_0402_50V7K  [C_0402]  38.58 22.84 0 top
PCV213  22U_B2_25VM_R90M  [C_B2]  24.97 26.66 90 top
PCV214  2.2U_0603_25VX7SK  [C_0603]  26.72 38.99 180 top
PCV215  2.2U_0603_25VX7SK  [C_0603]  28.21 40.39 0 top
PCV216  2.2U_0603_25VX7SK  [C_0603]  28.19 39.06 0 top
PCV217  2.2U_0603_25VX7SK  [C_0603]  33.01 40.4 270 bottom
PCV218  2.2U_0603_25VX7SK  [C_0603]  34.32 40.41 270 bottom
PCV219  2.2U_0603_25VX7SK  [C_0603]  36.92 40.45 270 bottom
PCV220  2.2U_0603_25VX7SK  [C_0603]  44.09 40.36 270 bottom
PCV221  2.2U_0603_25VX7SK  [C_0603]  41.62 40.4 270 bottom
PCV222  2.2U_0603_25VX7SK  [C_0603]  42.85 40.4 270 bottom
PCV223  2.2U_0603_25VX7SK  [C_0603]  51.3 40.44 0 top
PCV224  2.2U_0603_25VX7SK  [C_0603]  49.99 40.69 270 bottom
PCV225  2.2U_0603_25VX7SK  [C_0603]  51.21 40.69 270 bottom
PCV226  2.2U_0603_25VX7SK  [C_0603]  56.76 40.6 270 bottom
PCV227  2.2U_0603_25VX7SK  [C_0603]  54.28 40.82 270 bottom
PCV228  2.2U_0603_25VX7SK  [C_0603]  55.52 40.81 270 bottom
PCV229  2.2U_0603_25VX7SK  [C_0603]  67.26 40.63 270 bottom
PCV230  2.2U_0603_25VX7SK  [C_0603]  68.49 40.62 270 bottom
PCV231  2.2U_0603_25VX7SK  [C_0603]  64.73 43.91 90 bottom
PCV232  2.2U_0603_25VX7SK  [C_0603]  72.11 39.86 270 top
PCV233  2.2U_0603_25VX7SK  [C_0603]  75.54 40.48 270 bottom
PCV234  2.2U_0603_25VX7SK  [C_0603]  72.97 40.41 270 bottom
PCV235  2.2U_0603_25VX7SK  [C_0603]  70.4 75.82 90 bottom
PCV236  2.2U_0603_25VX7SK  [C_0603]  65.48 76.25 90 bottom
PCV237  2.2U_0603_25VX7SK  [C_0603]  69.16 75.83 90 bottom
PCV238  2.2U_0603_25VX7SK  [C_0603]  49.21 31.09 180 bottom
PCV239  2.2U_0603_25VX7SK  [C_0603]  49.21 32.29 180 bottom
PCV240  2.2U_0603_25VX7SK  [C_0603]  49.21 33.49 180 bottom
PCV241  2.2U_0603_25VX7SK  [C_0603]  49.23 34.69 180 bottom
PCV242  2.2U_0603_25VX7SK  [C_0603]  22.89 27.26 180 top
PCV243  2.2U_0603_25VX7SK  [C_0603]  25.32 33.75 90 top
PCV244  2.2U_0603_25VX7SK  [C_0603]  22.87 33.49 90 top
PCV245  2.2U_0603_25VX7SK  [C_0603]  24.08 33.48 90 top
PCW1  1U_0603_25V7K  [C_0603]  11.68 50.89 0 top
PCW2  0.1U_0402_25V6  [C_0402]  12.7 53.76 270 top
PCW3  0.1U_0402_25V6  [C_0402]  3.44 23.04 180 top
PCW4  0.1U_0402_25V6  [C_0402]  8.79 55.82 0 top
PCW5  2.2U_0603_6.3V6K  [C_0603]  5.92 55.87 180 top
PCW6  1U_0402_25V6K  [C_0402]  3.81 49.44 270 top
PCW7  2200P_0402_50V7K  [C_0402]  2.81 51.53 180 top
PCW8  0.015U_0402_25V7K  [C_0402]  10.98 55.75 270 top
PCW9  0.015U_0402_25V7K  [C_0402]  11.91 51.94 0 top
PCW10  0.015U_0402_25V7K  [C_0402]  10.36 48.86 0 top
PCW11  0.015U_0402_25V7K  [C_0402]  8.46 49.56 180 top
PCW12  0.015U_0402_25V7K  [C_0402]  6.54 48.72 90 top
PCW13  3300P_0402_25V7K  [C_0402]  12.51 49.49 270 top
PCW14  0.1U_0402_25V6  [C_0402]  2.86 60.85 0 bottom
PCW15  2.2U_0402_6.3V6M  [C_0402]  7.11 59.35 270 bottom
PCW16  2.2U_0402_6.3V6M  [C_0402]  5.65 58.44 90 bottom
PCW17  4.7U_0603_25VAK  [C_0603]  19 37.37 270 top
PCW18  4.7U_0603_25VAK  [C_0603]  3.67 58.22 180 top
PCW19  4.7U_0603_25VAK  [C_0603]  3.05 61.79 90 bottom
PCW20  4.7U_0603_25VAK  [C_0603]  20.47 39 180 top
PCW21  1U_0402_25V6K  [C_0402]  10.49 38.95 180 bottom
PCW22  0.1U_0603_25V7K  [C_0603]  2.31 59.45 0 top
PCW23  680P_0402_50V7K  [C_0402]  14.81 66.5 270 top
PCW24  1000P_0402_50V7K  [C_0402]  10.49 39.91 180 bottom
PCW25  2200P_0402_50V7K  [C_0402]  21.45 41.76 90 bottom
PCW26  560U_D2_2VM_R4.5M  [C_D2]  23.53 66.96 180 top
PCW28  560U_D2_2VM_R4.5M  [C_D2]  19.94 60.78 180 bottom
PCW29  0.1U_0402_25V6  [C_0402]  21.54 41.89 270 top
PCW30  2.2U_0402_6.3V6M  [C_0402]  12.34 39.8 0 top
PCW31  2.2U_0402_6.3V6M  [C_0402]  14.14 41.85 90 top
PCW32  4.7U_0603_25VAK  [C_0603]  20.22 37.37 270 top
PCW33  4.7U_0603_25VAK  [C_0603]  21.55 40.07 270 top
PCW34  4.7U_0603_25VAK  [C_0603]  2.9 59.76 0 bottom
PCW35  4.7U_0603_25VAK  [C_0603]  3.56 55.98 180 top
PCW36  1U_0402_25V6K  [C_0402]  2.95 58.66 0 bottom
PCW37  0.1U_0603_25V7K  [C_0603]  14.2 38.17 0 top
PCW38  680P_0402_50V7K  [C_0402]  16.76 47.59 270 bottom
PCW39  1000P_0402_50V7K  [C_0402]  3.05 57.08 180 top
PCW40  2200P_0402_50V7K  [C_0402]  21.53 42.73 90 top
PCW41  0.1U_0402_25V6  [C_0402]  17.45 56.42 0 bottom
PCW42  0.1U_0402_25V6  [C_0402]  17.21 55.15 270 bottom
PCW43  0.1U_0402_25V6  [C_0402]  21.84 52.73 180 bottom
PCW44  0.1U_0402_25V6  [C_0402]  23.05 51.46 90 bottom
PCZ1  0.1U_0402_25V6  [C_0402]  139.26 133.58 270 top
PCZ2  0.1U_0402_25V6  [C_0402]  140.27 121.94 90 top
PCZ3  0.1U_0402_25V6  [C_0402]  137.86 132.3 180 top
PCZ5  0.1U_0402_25V6  [C_0402]  138.37 124.28 90 top
PCZ6  0.1U_0402_25V6  [C_0402]  140.14 133.58 270 top
PCZ7  0.1U_0402_25V6  [C_0402]  141.03 133.58 270 top
PCZ10  10U_0402_6.3V6M  [C_0402]  145.47 126.39 0 bottom
PCZ11  0.22U_0402_25V6K  [C_0402]  142.11 130.19 90 bottom
PCZ12  0.22U_0402_25V6K  [C_0402]  141.99 124.74 90 bottom
PCZ13  0.01UF_0402_25V7K  [C_0402]  148.4 134.84 270 top
PCZ14  100P_0402_50V8J  [C_0402]  149.05 129.5 180 bottom
PCZ15  100P_0402_50V8J  [C_0402]  142.05 133.58 270 bottom
PCZ16  100P_0402_50V8J  [C_0402]  141.54 121.94 90 top
PCZ17  47P_0402_50V8J  [C_0402]  144.51 132.62 0 bottom
PCZ18  47P_0402_50V8J  [C_0402]  143.13 121.94 90 bottom
PCZ19  470P_0402_50V8J  [C_0402]  143.95 131.1 270 bottom
PCZ20  470P_0402_50V8J  [C_0402]  143.51 135.85 0 top
PCZ21  470P_0402_50V8J  [C_0402]  145.54 128.48 90 bottom
PCZ22  470P_0402_50V8J  [C_0402]  144.48 120.67 180 top
PCZ23  470P_0402_50V8J  [C_0402]  145.29 122.85 270 bottom
PCZ24  1000P_0402_50V7K  [C_0402]  148.84 128.78 180 top
PCZ25  1000P_0402_50V7K  [C_0402]  149.05 132.11 180 top
PCZ26  1000P_0402_50V7K  [C_0402]  149.76 130.77 270 top
PCZ27  680P_0402_50V7K  [C_0402]  142.05 133.58 270 top
PCZ28  1000P_0402_50V7K  [C_0402]  149.05 131.28 180 bottom
PCZ29  1000P_0402_50V7K  [C_0402]  147.45 122.85 270 top
PCZ30  0.01U_0402_50V7K  [C_0402]  136.96 130.65 0 top
PCZ31  2200P_0402_50V7K  [C_0402]  149.05 130.39 180 bottom
PCZ32  2200P_0402_50V7K  [C_0402]  146.49 122.85 270 top
PCZ33  2200P_0402_50V7K  [C_0402]  149.05 133 180 top
PCZ34  2200P_0402_50V7K  [C_0402]  144.51 133.57 0 bottom
PCZ35  2200P_0402_50V7K  [C_0402]  149.29 134.85 270 top
PCZ36  2200P_0402_50V7K  [C_0402]  143.38 121.94 90 top
PCZ37  470P_0402_50V7K  [C_0402]  141.55 121 180 top
PCZ38  0.015U_0402_25V7K  [C_0402]  147.93 129.67 0 top
PCZ39  3300P_0402_25V7K  [C_0402]  148.64 135.66 0 bottom
PCZ40  2.2U_0402_10V6M  [C_0402]  137.92 129.38 180 bottom
PCZ47  0.1U_0402_25V6  [C_0402]  127.08 125.82 180 bottom
PCZ48  0.1U_0402_25V6  [C_0402]  127.03 125.81 180 top
PCZ49  10U_0603_25V6M  [C_0603]  82.42 130.16 270 top
PCZ50  10U_0603_25V6M  [C_0603]  127.9 124.29 180 bottom
PCZ52  10U_0603_25V6M  [C_0603]  80.71 130.16 270 bottom
PCZ53  10U_0603_25V6M  [C_0603]  127.95 124.29 180 top
PCZ55  2.2U_0402_10V6M  [C_0402]  95.44 133.01 270 bottom
PCZ56  2.2U_0402_10V6M  [C_0402]  88.01 132.95 270 bottom
PCZ57  0.1U_0402_50V7K  [C_0402]  93.03 134.7 90 top
PCZ58  0.1U_0402_50V7K  [C_0402]  93.03 137.53 270 top
PCZ59  0.22U_0603_25V7K  [C_0603]  82.55 133.25 0 bottom
PCZ60  0.22U_0603_25V7K  [C_0603]  90.11 133.44 0 bottom
PCZ61  2.2U_0402_25V6M  [C_0402]  87.06 132.95 270 bottom
PCZ62  2.2U_0402_25V6M  [C_0402]  94.55 133.01 270 bottom
PCZ63  1U_0402_25V6K  [C_0402]  149.97 68.93 0 top
PCZ64  1U_0402_25V6K  [C_0402]  82.74 131.27 90 bottom
PCZ65  2.2U_0402_25V6M  [C_0402]  100.65 134.84 0 top
PCZ66  390P_0402_50V7K  [C_0402]  87.44 125.71 90 bottom
PCZ67  390P_0402_50V7K  [C_0402]  92.23 125.75 90 bottom
PCZ68  1000P_0402_50V7K  [C_0402]  149.81 78.13 180 top
PCZ69  1000P_0402_50V7K  [C_0402]  149.97 69.88 0 top
PCZ70  2200P_0402_50V7K  [C_0402]  128.13 125.76 0 top
PCZ71  2200P_0402_50V7K  [C_0402]  98.95 130.96 180 top
PCZ73  0.01U_0402_16V7K  [C_0402]  92.34 135.85 180 bottom
PCZ74  100U_D3L_25VM_R60M  [C_T521D107M025ATE060]  103.51 137.07 0 top
PCZ75  100U_D3L_25VM_R60M  [C_T521D107M025ATE060]  112.89 137.06 0 top
PCZ80  0.1U_0402_25V6  [C_0402]  126.93 134.37 90 top
PCZ81  0.1U_0402_25V6  [C_0402]  98.95 131.85 180 bottom
PCZ84  10U_0603_25V6M  [C_0603]  125.6 134.2 180 bottom
PCZ85  10U_0603_25V6M  [C_0603]  82.42 130.16 270 bottom
PCZ86  10U_0603_25V6M  [C_0603]  125.63 134.2 180 top
PCZ87  10U_0603_25V6M  [C_0603]  98.55 129.72 270 top
PCZ88  2.2U_0402_10V6M  [C_0402]  104.08 133.07 270 bottom
PCZ89  2.2U_0402_10V6M  [C_0402]  112.39 132.98 270 bottom
PCZ90  0.1U_0402_50V7K  [C_0402]  133.38 135.56 0 top
PCZ91  0.1U_0402_50V7K  [C_0402]  129.79 135.59 0 bottom
PCZ92  0.22U_0603_25V7K  [C_0603]  107 133.44 0 bottom
PCZ93  0.22U_0603_25V7K  [C_0603]  98.68 133.25 0 bottom
PCZ94  2.2U_0402_25V6M  [C_0402]  111.32 132.06 90 bottom
PCZ95  1U_0402_25V6K  [C_0402]  90.3 130.47 270 bottom
PCZ96  1U_0402_25V6K  [C_0402]  90.3 130.47 270 top
PCZ97  2.2U_0402_25V6M  [C_0402]  103.19 133.07 270 bottom
PCZ98  2.2U_0402_25V6M  [C_0402]  130.87 129.39 270 top
PCZ99  390P_0402_50V7K  [C_0402]  108.01 125.44 90 bottom
PCZ100  390P_0402_50V7K  [C_0402]  100.44 125.72 90 bottom
PCZ101  1000P_0402_50V7K  [C_0402]  98.95 130.96 180 bottom
PCZ102  1000P_0402_50V7K  [C_0402]  107.33 131.16 180 bottom
PCZ103  2200P_0402_50V7K  [C_0402]  126.94 134.38 90 bottom
PCZ104  2200P_0402_50V7K  [C_0402]  82.74 131.27 90 top
PCZ106  0.01U_0402_16V7K  [C_0402]  133.41 133.14 90 bottom
PCZ109  0.1U_0402_25V6  [C_0402]  107.33 131.16 180 top
PCZ110  0.1U_0402_25V6  [C_0402]  90.3 131.4 90 top
PCZ111  10U_0603_25V6M  [C_0603]  106.93 129.91 270 bottom
PCZ113  10U_0603_25V6M  [C_0603]  106.93 129.92 270 top
PCZ114  10U_0603_25V6M  [C_0603]  98.55 129.72 270 bottom
PCZ116  10U_0603_25V6M  [C_0603]  91.35 130.9 0 bottom
PCZ117  2.2U_0402_10V6M  [C_0402]  127.39 116.42 180 top
PCZ118  2.2U_0402_10V6M  [C_0402]  123.95 126.01 270 top
PCZ119  0.1U_0402_50V7K  [C_0402]  135.78 127.54 180 bottom
PCZ120  0.1U_0402_50V7K  [C_0402]  132.33 125.52 270 bottom
PCZ121  0.22U_0603_25V7K  [C_0603]  132.21 121.12 180 top
PCZ122  0.22U_0603_25V7K  [C_0603]  129.41 130.96 90 bottom
PCZ123  2.2U_0402_25V6M  [C_0402]  131.65 118.58 180 top
PCZ124  1U_0402_25V6K  [C_0402]  81.72 131.27 90 top
PCZ125  2.2U_0402_25V6M  [C_0402]  129.22 129.77 270 top
PCZ126  1U_0402_25V6K  [C_0402]  81.72 131.27 90 bottom
PCZ127  2.2U_0402_25V6M  [C_0402]  132.21 122.52 180 top
PCZ128  390P_0402_50V7K  [C_0402]  120.08 129.76 0 bottom
PCZ129  390P_0402_50V7K  [C_0402]  123.32 124.61 270 bottom
PCZ130  1000P_0402_50V7K  [C_0402]  129.12 125.77 180 bottom
PCZ131  1000P_0402_50V7K  [C_0402]  90.3 131.4 90 bottom
PCZ132  2200P_0402_50V7K  [C_0402]  107.33 132.11 180 top
PCZ133  2200P_0402_50V7K  [C_0402]  98.95 131.85 180 top
PCZ134  0.01U_0402_16V7K  [C_0402]  135 124.65 270 bottom
PCZ135  0.01U_0402_16V7K  [C_0402]  136.02 123.74 90 bottom
PCZ138  22U_0603_6.3V6M  [C_0603]  120.51 94.13 0 bottom
PCZ139  22U_0603_6.3V6M  [C_0603]  107.52 101.15 180 bottom
PCZ140  22U_0603_6.3V6M  [C_0603]  119.21 102.62 180 bottom
PCZ141  22U_0603_6.3V6M  [C_0603]  104.08 104.68 180 bottom
PCZ142  22U_0603_6.3V6M  [C_0603]  108.81 102.59 0 bottom
PCZ143  22U_0603_6.3V6M  [C_0603]  108.81 101.2 0 bottom
PCZ144  22U_0603_6.3V6M  [C_0603]  113.18 100.89 180 bottom
PCZ145  22U_0603_6.3V6M  [C_0603]  114.87 102.59 0 bottom
PCZ146  22U_0603_6.3V6M  [C_0603]  114.9 101.31 0 bottom
PCZ147  22U_0603_6.3V6M  [C_0603]  119.08 94.07 180 bottom
PCZ148  22U_0603_6.3V6M  [C_0603]  107.53 102.61 180 bottom
PCZ149  22U_0603_6.3V6M  [C_0603]  112.98 94.31 180 bottom
PCZ150  22U_0603_6.3V6M  [C_0603]  104.08 101.06 180 bottom
PCZ151  22U_0603_6.3V6M  [C_0603]  120.62 102.58 0 bottom
PCZ152  22U_0603_6.3V6M  [C_0603]  141.86 117.29 90 top
PCZ153  22U_0603_6.3V6M  [C_0603]  104.08 103.47 180 bottom
PCZ154  22U_0603_6.3V6M  [C_0603]  119.24 101.32 180 bottom
PCZ155  22U_0603_6.3V6M  [C_0603]  108.79 94.49 0 bottom
PCZ156  22U_0603_6.3V6M  [C_0603]  140.59 117.29 90 top
PCZ157  22U_0603_6.3V6M  [C_0603]  104.08 102.26 180 bottom
PCZ158  22U_0603_6.3V6M  [C_0603]  114.62 94.27 0 bottom
PCZ159  47U_0805_6.3V6M  [C_0805]  113.33 102.42 180 bottom
PCZ160  47U_0603_6.3V6M  [C_0603]  144.89 113.36 90 top
PCZ161  47U_0805_6.3V6M  [C_0805]  130.77 96.04 180 bottom
PCZ162  47U_0603_6.3V6M  [C_0603]  106.72 115.2 180 top
PCZ163  47U_0805_6.3V6M  [C_0805]  125.83 101.69 0 bottom
PCZ164  47U_0603_6.3V6M  [C_0603]  145.58 116.65 90 top
PCZ165  47U_0805_6.3V6M  [C_0805]  107.53 94.64 180 bottom
PCZ166  47U_0805_6.3V6M  [C_0805]  130.77 101.75 180 bottom
PCZ167  47U_0805_6.3V6M  [C_0805]  130.77 99.79 180 bottom
PCZ168  47U_0805_6.3V6M  [C_0805]  113.37 104.23 180 bottom
PCZ169  47U_0603_6.3V6M  [C_0603]  107.86 115.22 0 top
PCZ170  47U_0805_6.3V6M  [C_0805]  114.59 104.23 0 bottom
PCZ171  47U_0805_6.3V6M  [C_0805]  140.78 93.59 270 top
PCZ172  47U_0805_6.3V6M  [C_0805]  125.83 103.53 0 bottom
PCZ173  47U_0603_6.3V6M  [C_0603]  119.86 116.17 0 top
PCZ174  47U_0805_6.3V6M  [C_0805]  125.83 99.79 0 bottom
PCZ175  47U_0603_6.3V6M  [C_0603]  143.32 116.72 90 top
PCZ176  47U_0603_6.3V6M  [C_0603]  112.42 115.22 180 top
PCZ177  47U_0805_6.3V6M  [C_0805]  130.77 97.94 180 bottom
PCZ178  47U_0805_6.3V6M  [C_0805]  124.96 94.77 90 bottom
PCZ179  47U_0805_6.3V6M  [C_0805]  130.77 103.53 180 bottom
PCZ180  47U_0805_6.3V6M  [C_0805]  127.06 94.82 90 bottom
PCZ181  47U_0603_6.3V6M  [C_0603]  139 117.39 90 top
PCZ182  1U_0201_6.3V6M  [C_0201]  115.14 99.93 0 bottom
PCZ183  1U_0201_6.3V6M  [C_0201]  120.93 98.71 0 bottom
PCZ184  1U_0201_6.3V6M  [C_0201]  118.85 95.98 180 bottom
PCZ185  1U_0201_6.3V6M  [C_0201]  118.85 97.88 180 bottom
PCZ186  1U_0201_6.3V6M  [C_0201]  120.93 100.61 0 bottom
PCZ187  1U_0201_6.3V6M  [C_0201]  112.84 99.34 180 bottom
PCZ188  1U_0201_6.3V6M  [C_0201]  114.53 99.91 180 bottom
PCZ189  1U_0201_6.3V6M  [C_0201]  114.53 99.28 180 bottom
PCZ190  1U_0201_6.3V6M  [C_0201]  107.02 96.71 180 bottom
PCZ191  1U_0201_6.3V6M  [C_0201]  108.97 99.08 0 bottom
PCZ192  1U_0201_6.3V6M  [C_0201]  112.86 95.34 180 bottom
PCZ193  1U_0201_6.3V6M  [C_0201]  108.99 97.03 0 bottom
PCZ194  1U_0201_6.3V6M  [C_0201]  112.84 97.37 180 bottom
PCZ195  1U_0201_6.3V6M  [C_0201]  115.11 97.26 0 bottom
PCZ196  1U_0201_6.3V6M  [C_0201]  115.11 97.92 0 bottom
PCZ197  1U_0201_6.3V6M  [C_0201]  118.85 99.79 180 bottom
PCZ198  1U_0201_6.3V6M  [C_0201]  112.85 96.01 180 bottom
PCZ199  1U_0201_6.3V6M  [C_0201]  109.02 96.34 0 bottom
PCZ200  1U_0201_6.3V6M  [C_0201]  112.84 98.05 180 bottom
PCZ201  1U_0201_6.3V6M  [C_0201]  120.93 97.44 0 bottom
PCZ202  1U_0201_6.3V6M  [C_0201]  120.93 96.8 0 bottom
PCZ203  1U_0201_6.3V6M  [C_0201]  118.85 100.42 180 bottom
PCZ204  1U_0201_6.3V6M  [C_0201]  118.85 96.61 180 bottom
PCZ205  1U_0201_6.3V6M  [C_0201]  118.85 98.52 180 bottom
PCZ206  1U_0201_6.3V6M  [C_0201]  120.93 99.98 0 bottom
PCZ207  1U_0201_6.3V6M  [C_0201]  115.15 95.35 0 bottom
PCZ208  1U_0201_6.3V6M  [C_0201]  114.53 98.64 180 bottom
PCZ209  1U_0201_6.3V6M  [C_0201]  114.53 97.37 180 bottom
PCZ210  1U_0201_6.3V6M  [C_0201]  107.01 97.39 180 bottom
PCZ211  1U_0201_6.3V6M  [C_0201]  120.93 98.07 0 bottom
PCZ212  1U_0201_6.3V6M  [C_0201]  115.16 99.27 0 bottom
PCZ213  1U_0201_6.3V6M  [C_0201]  115.14 98.58 0 bottom
PCZ214  1U_0201_6.3V6M  [C_0201]  118.85 97.25 180 bottom
PCZ215  1U_0201_6.3V6M  [C_0201]  118.85 99.15 180 bottom
PCZ216  1U_0201_6.3V6M  [C_0201]  120.93 99.34 0 bottom
PCZ217  1U_0201_6.3V6M  [C_0201]  115.14 95.99 0 bottom
PCZ218  1U_0201_6.3V6M  [C_0201]  114.53 98.01 180 bottom
PCZ219  1U_0201_6.3V6M  [C_0201]  114.53 96.74 180 bottom
PCZ220  1U_0201_6.3V6M  [C_0201]  107.02 98.07 180 bottom
PCZ221  1U_0201_6.3V6M  [C_0201]  108.98 97.7 0 bottom
PCZ222  1U_0201_6.3V6M  [C_0201]  112.84 96.7 180 bottom
PCZ223  1U_0201_6.3V6M  [C_0201]  109 95.65 0 bottom
PCZ224  1U_0201_6.3V6M  [C_0201]  112.84 98.73 180 bottom
PCZ225  1U_0201_6.3V6M  [C_0201]  115.14 96.61 0 bottom
PCZ226  1U_0201_6.3V6M  [C_0201]  112.84 99.94 180 bottom
PCZ227  1U_0201_6.3V6M  [C_0201]  120.93 96.17 0 bottom
PCZ228  1U_0201_6.3V6M  [C_0201]  112.56 114.01 180 top
PCZ229  1U_0201_6.3V6M  [C_0201]  108.98 98.39 0 bottom
PCZ230  10U_0402_6.3V6M  [C_0402]  90.11 114.4 270 top
PCZ231  10U_0402_6.3V6M  [C_0402]  120.76 101.37 0 bottom
PCZ232  10U_0402_6.3V6M  [C_0402]  119.04 95.2 180 bottom
PCZ233  10U_0402_6.3V6M  [C_0402]  92.84 114.34 270 top
PCZ234  10U_0402_6.3V6M  [C_0402]  120.76 95.33 0 bottom
PCZ235  10U_0402_6.3V6M  [C_0402]  109.08 99.99 0 bottom
PCZ236  10U_0402_6.3V6M  [C_0402]  107.34 100.02 180 bottom
PCZ237  10U_0402_6.3V6M  [C_0402]  107.35 98.98 180 bottom
PCZ238  10U_0402_6.3V6M  [C_0402]  120.26 114.84 0 top
PCZ239  10U_0402_6.3V6M  [C_0402]  107.2 95.98 180 bottom
PCZ240  22U_0603_6.3V6M  [C_0603]  119.21 104.23 180 bottom
PCZ241  22U_0603_6.3V6M  [C_0603]  91.5 114.8 270 top
PCZ242  22U_0603_6.3V6M  [C_0603]  120.62 104.23 0 bottom
PCZ243  22U_0603_6.3V6M  [C_0603]  108.75 104.23 0 bottom
PCZ244  22U_0603_6.3V6M  [C_0603]  107.53 104.23 180 bottom
PCZ246  470U_D2_2VM_R4.5M  [C_D2]  141.54 95.33 270 bottom
PCZ248  470U_D2_2VM_R4.5M  [C_D2]  114.32 119.22 180 bottom
PCZ249  470U_D2_2VM_R4.5M  [C_D2]  91.85 119.22 180 bottom
PCZ251  0.1U_0402_25V6  [C_0402]  150.13 128.59 270 top
PCZ252  0.01U_0402_16V7K  [C_0402]  139.09 136.3 180 bottom
PCZ253  0.01U_0402_16V7K  [C_0402]  140.14 136.26 0 bottom
PD1  -  [PESD24VS2UT_SOT23-3]  14.83 25.92 270 top
PD2  -  [TVNST52302AB0_SOT523-3]  28.59 2.96 90 top
PD3  -  [TVNST52302AB0_SOT523-3]  25.26 2.4 180 top
PD4  -  [BAS40CW_SOT323-3]  17.57 7.43 0 top
PD501  -  [RB751V-40_SOD323-2]  39.62 7.08 90 bottom
PD502  -  [BAS40CW_SOT323-3]  41.77 7.72 0 bottom
PD1202  -  [SX34F_SMAF2]  131.16 42.51 0 top
PDB1  -  [BAT54CW_SOT323-3]  42.74 13.43 90 top
PDM01  -  [RB751V-40_SOD323-2]  150.32 39.11 270 top
PDV01  -  [RB751V-40_SOD323-2]  62.67 30.06 90 bottom
PH01  100K_0402_1%_B25/50 4250K  [R_0402]  103.8 94.1 180 bottom
PHV01  10K_0402_1%_TSM0A103F34D1RZ  [R_0402]  30.98 57.37 0 top
PHZ01  100K_0402_1%_TSM0B104F4251RZ  [R_0402]  145.34 111.22 0 top
PHZ02  220K_0402_5%_TSM0B224J4702RE  [R_0402]  141.47 96.61 0 top
PHZ03  220K_0402_5%_TSM0B224J4702RE  [R_0402]  148.64 89.49 0 top
PHZ04  220K_0402_5%_TSM0B224J4702RE  [R_0402]  81.98 123.27 90 top
PHZ05  220K_0402_5%_TSM0B224J4702RE  [R_0402]  81.98 125.83 270 top
PJP42  -  [JUMP_43X79]  70.34 8.41 180 top
PJP81  -  [JUMP_43X118]  27.34 30.63 180 top
PJP301  JUMP_43X79  [JUMP_43X79-NPM]  65.32 32.87 270 top
PJP302  -  [JUMP_43X118]  67.52 18.51 0 bottom
PJP303  -  [JUMP_43X39]  61.26 23.52 180 top
PJP501  JUMP_43X79  [JUMP_43X79-NPM]  60.93 32.92 270 top
PJP502  -  [JUMP_43X118]  58.49 13.99 0 bottom
PJP503  JUMP_43X39  [JUMP_43X39-NPM]  48.55 21.87 180 top
PJP1101  -  [JUMP_43X79]  65.64 111.28 180 bottom
PJP1803  -  [JUMP_43X79]  60.79 8.92 0 top
PJP2501  -  [JUMP_43X39]  87.42 55.44 90 top
PJP2502  -  [JUMP_43X79]  90.83 68.99 0 top
PJP2503  -  [JUMP_43X39]  142.44 39.27 180 bottom
PJP2504  -  [JUMP_43X39]  128.86 43.95 180 top
PJPDC1  OCTEK_WTB-12GCBWAB-U  [OCTEK_WTB-12GCBWAB-U_12P]  8.95 35.63 90 bottom
PJPG01  -  [JUMP_43X79]  150.65 81.41 180 top
PJPG02  -  [JUMP_43X39]  149.35 104.04 270 top
PJPH01  JUMP_43X39  [JUMP_43X39-NPM]  137.54 23.59 270 top
PJPH02  -  [JUMP_43X118]  127.95 39.8 90 bottom
PJPH03  JUMP_43X39  [JUMP_43X39-NPM]  132.31 45.96 90 top
PJPH04  -  [JUMP_43X118]  119.95 52.38 180 bottom
PJPM01  JUMP_43X39  [JUMP_43X39-NPM]  139.44 50.23 90 bottom
PJPM03  -  [JUMP_43X118]  145.71 67.59 180 bottom
PJPM04  -  [JUMP_43X39]  142.94 51.58 90 top
PL11  9A Z80 10M 1812_2P  [9A_Z80_1812_2P]  16.13 33.04 270 bottom
PL12  9A Z80 10M 1812_2P  [9A_Z80_1812_2P]  12.32 33.04 270 bottom
